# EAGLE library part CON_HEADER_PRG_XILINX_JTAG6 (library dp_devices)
6-pin Xilinx JTAG programming header
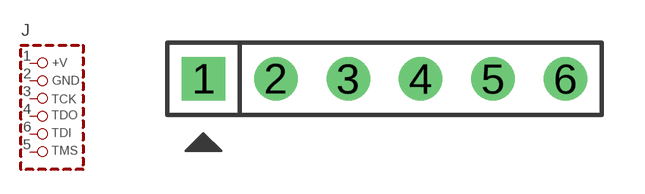
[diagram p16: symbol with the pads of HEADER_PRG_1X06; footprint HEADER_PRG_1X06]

Designator prefix J

## CON_HEADER_PRG_XILINX_JTAG6  [HEADER_PRG_1X06]
1  +V  pas
2  GND  pas
3  TCK  pas
4  TDO  pas
5  TMS  pas
6  TDI  pas

## Footprint HEADER_PRG_1X06 (pad centres in mm)
drill 1.016 square: 1 -6.35,0
drill 1.016 round: 2 -3.81,0; 3 -1.27,0; 4 1.27,0; 5 3.81,0; 6 6.35,0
